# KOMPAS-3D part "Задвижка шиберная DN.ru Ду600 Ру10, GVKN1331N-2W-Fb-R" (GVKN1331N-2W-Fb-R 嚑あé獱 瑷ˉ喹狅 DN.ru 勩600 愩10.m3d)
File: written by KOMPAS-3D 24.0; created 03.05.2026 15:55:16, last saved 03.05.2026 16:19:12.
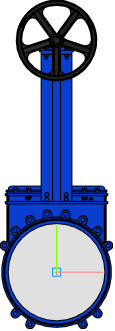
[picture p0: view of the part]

Document properties: Автор: DN.ru; Полное имя файла: C:\Работа\GVKN1331N-2W-Fb-R Задвижка шиберная DN.ru Ду400-600 Ру10\DN600\GVKN1331N-2W-Fb-R Задвижка шиберная DN.ru Ду600 Ру10.m3d

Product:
- Part/product: Задвижка шиберная DN.ru Ду600 Ру10  | designation GVKN1331N-2W-Fb-R
    Масса: 281
    Раздел спецификации: Прочие изделия
    Примечание: D040-07841

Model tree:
1. Операция без истории:1

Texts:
  GVKN1331N-2W-Fb-R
